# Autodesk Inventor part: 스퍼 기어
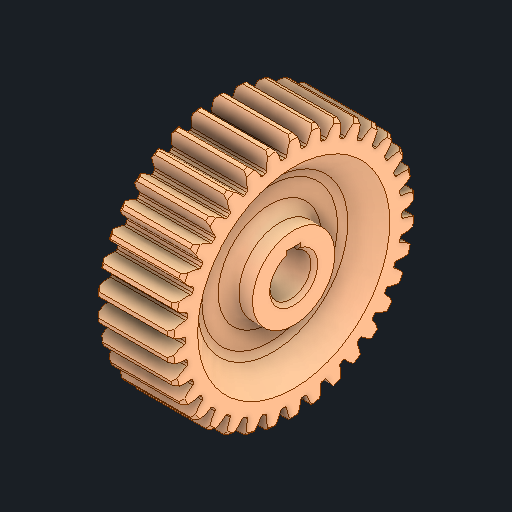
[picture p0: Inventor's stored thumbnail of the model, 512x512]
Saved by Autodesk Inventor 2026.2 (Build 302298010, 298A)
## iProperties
Created: 2026-03
Part Number: 스퍼 기어
Material: 강철, 합금
Document SubType Name: Modeling
Designer: PC2-02
Density: 7.73 g/cm^3
Appearance: 기본값
Author: jhkim
Sending System: Autodesk Inventor 2026
Preprocessor: ST-DEVELOPER v20.1
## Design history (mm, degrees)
feature "솔리드1"
node "솔리드2"
